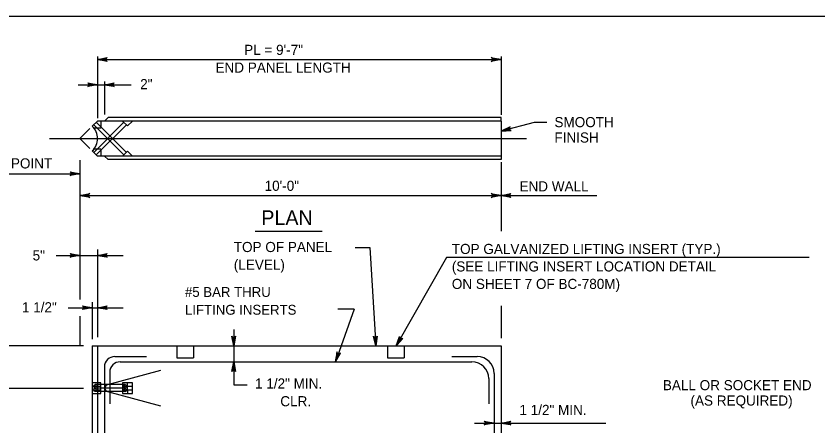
# Model space of a CAD drawing. Extents: x 3385 to 6532, y -616 to 1166.
# Drawn here: x 5875.8 to 6119.6, y 432.2 to 556.7 of the extents above; entities that cross this region are included whole.
import ezdxf

# ---------------------------------------------------------------- set-up
doc = ezdxf.new("R2010")
doc.units = 0
doc.layers.add('1', color=7, linetype='Continuous')
doc.layers.add('2', color=7, linetype='Continuous')

msp = doc.modelspace()

# ---------------------------------------------------------------- linework, layer by layer
at = {"layer": '1'}
for p, q in [((5900.6, 544.41), (5900.6, 525.64)), ((6023.26, 544.41), (6023.26, 526.72)), ((5900.6, 543.5), (6023.26, 543.5)), ((5902.73, 536.78), (5902.73, 526.81)), ((5894.73, 535.82), (5910.81, 535.82)), ((5899.03, 523.25), (5900.6, 524.82)), ((5899.45, 515.31), (5908.61, 524.46)), ((5900.24, 524.46), (5909.4, 515.31)), ((6023.26, 524.82), (5900.6, 524.82)), ((5901.65, 524.82), (5901.65, 522.69)), ((5902.73, 524.82), (5903.8, 525.89)), ((6023.26, 525.89), (5903.8, 525.89)), ((5909.76, 523.31), (5908.25, 524.82)), ((5909.76, 523.31), (5911.27, 524.82)), ((6023.26, 524.82), (6023.26, 525.89)), ((6023.26, 524.82), (6023.26, 514.16)), ((6033.37, 524.4), (6023.26, 521.72)), ((6037.2, 524.4), (6033.37, 524.4)), ((5895.27, 519.49), (5898.3, 522.53)), ((5899.45, 523.67), (5908.61, 514.51)), ((5901.65, 522.69), (5899.52, 522.69)), ((5900.24, 514.51), (5909.4, 523.67)), ((5886.06, 519.49), (6030.95, 519.49)), ((5895.27, 519.49), (5898.3, 516.46)), ((5899.03, 515.73), (5900.6, 514.16)), ((5901.65, 516.29), (5899.52, 516.29)), ((5901.65, 516.29), (5901.65, 514.16)), ((5909.76, 515.66), (5908.25, 514.16)), ((5909.76, 515.66), (5911.27, 514.16)), ((5895.27, 512.95), (5895.27, 470.58)), ((6023.26, 514.16), (5900.6, 514.16)), ((5902.73, 514.16), (5903.8, 513.09)), ((6023.26, 513.09), (5903.8, 513.09)), ((6023.26, 514.16), (6023.26, 513.09)), ((6023.26, 512.28), (6023.26, 491.33)), ((5860.61, 508.82), (5895.27, 508.82)), ((5895.27, 502.2), (6023.26, 502.2)), ((6023.26, 502.2), (6052.41, 502.2)), ((5948.5, 491.37), (5968.87, 491.37)), ((5900.59, 485.76), (5900.59, 459.17)), ((5978.88, 486.43), (5983.34, 486.43)), ((5983.34, 486.43), (5985.2, 456.51)), ((5888.09, 484.02), (5908.38, 484.02)), ((6006.69, 483.34), (5991.43, 456.51)), ((6116.94, 483.34), (6006.69, 483.34)), ((5891.74, 468.14), (5908.38, 468.14)), ((5899.03, 469.79), (5899.03, 458.62)), ((6023.26, 468.68), (6023.26, 458.93)), ((5895.27, 465.6), (5895.27, 456.83)), ((5978.57, 467.64), (5972.94, 451.71)), ((5978.57, 467.64), (5973.68, 467.64)), ((5942, 461.55), (5942, 444.73)), ((5896.39, 456.51), (5848.64, 456.51)), ((5899.03, 456.51), (6023.26, 456.51)), ((5899.03, 456.51), (5899.03, 301.32)), ((5900.59, 456.51), (5900.59, 301.32)), ((5924.71, 456.51), (5924.71, 452.93)), ((5929.83, 456.51), (5929.83, 452.93)), ((5988.7, 456.51), (5988.7, 452.93)), ((5993.82, 456.51), (5993.82, 452.93)), ((6023.26, 456.51), (6023.26, 301.32)), ((5905.92, 453.31), (5915.52, 453.31)), ((5907.52, 451.71), (6014.41, 451.71)), ((5924.71, 452.93), (5929.83, 452.93)), ((5988.7, 452.93), (5993.82, 452.93)), ((6008.33, 453.31), (6016.01, 453.31)), ((5902.72, 450.11), (5902.72, 307.72)), ((5919.73, 449.05), (5903.62, 444.73)), ((5904.32, 448.51), (5904.32, 438.91)), ((6019.53, 446.59), (6019.53, 438.91)), ((6021.13, 448.19), (6021.13, 309.64)), ((5848.87, 443.71), (5896.39, 443.71)), ((5909, 444.78), (5899.85, 444.78)), ((5909, 443.71), (5899.85, 443.71)), ((5909.76, 443.18), (5909.76, 445.31)), ((5942, 444.73), (5946.05, 444.73)), ((5909, 442.65), (5899.85, 442.65)), ((5903.62, 442.67), (5919.73, 438.35)), ((5909.76, 443.18), (5909.76, 442.11)), ((6015.17, 433.1), (6055.09, 433.1))]:
    msp.add_line(p, q, dxfattribs=at)
for points in [[(5900.6, 543.5), (5903.58, 544.06), (5903.35, 543.9), (5903.23, 543.7), (5903.2, 543.5), (5903.23, 543.3), (5903.35, 543.1), (5903.58, 542.94), (5900.6, 543.5), (5903.35, 543.1), (5903.23, 543.3), (5900.6, 543.5), (5903.2, 543.5), (5903.23, 543.7), (5900.6, 543.5), (5903.35, 543.9)], [(6023.26, 543.5), (6020.28, 542.94), (6020.51, 543.1), (6020.63, 543.3), (6020.66, 543.5), (6020.63, 543.7), (6020.51, 543.9), (6020.28, 544.06), (6023.26, 543.5), (6020.51, 543.9), (6020.63, 543.7), (6023.26, 543.5), (6020.66, 543.5), (6020.63, 543.3), (6023.26, 543.5), (6020.51, 543.1)], [(5900.6, 535.82), (5897.62, 535.26), (5897.85, 535.42), (5897.96, 535.62), (5898, 535.82), (5897.96, 536.02), (5897.85, 536.22), (5897.62, 536.38), (5900.6, 535.82), (5897.85, 536.22), (5897.96, 536.02), (5900.6, 535.82), (5898, 535.82), (5897.96, 535.62), (5900.6, 535.82), (5897.85, 535.42)], [(5902.73, 535.82), (5905.72, 536.38), (5905.49, 536.22), (5905.37, 536.02), (5905.33, 535.82), (5905.37, 535.62), (5905.49, 535.42), (5905.72, 535.26), (5902.73, 535.82), (5905.49, 535.42), (5905.37, 535.62), (5902.73, 535.82), (5905.33, 535.82), (5905.37, 536.02), (5902.73, 535.82), (5905.49, 536.22)], [(6023.26, 521.72), (6026.29, 521.95), (6026.16, 521.99), (6026.03, 522.04), (6025.94, 522.12), (6025.86, 522.2), (6025.82, 522.3), (6025.78, 522.39), (6025.77, 522.49), (6025.76, 522.59), (6025.79, 522.7), (6025.82, 522.81), (6025.91, 522.92), (6026, 523.03), (6023.26, 521.72), (6025.91, 522.92), (6025.82, 522.81), (6023.26, 521.72), (6025.79, 522.7), (6025.76, 522.59), (6023.26, 521.72), (6025.77, 522.49), (6025.78, 522.39), (6023.26, 521.72), (6025.82, 522.3), (6025.86, 522.2), (6023.26, 521.72), (6025.94, 522.12), (6026.03, 522.04), (6023.26, 521.72), (6026.16, 521.99)], [(5895.27, 508.82), (5892.28, 508.26), (5892.51, 508.42), (5892.63, 508.62), (5892.67, 508.82), (5892.63, 509.02), (5892.51, 509.22), (5892.28, 509.38), (5895.27, 508.82), (5892.51, 509.22), (5892.63, 509.02), (5895.27, 508.82), (5892.67, 508.82), (5892.63, 508.62), (5895.27, 508.82), (5892.51, 508.42)], [(5895.27, 502.2), (5898.25, 502.76), (5898.02, 502.6), (5897.9, 502.4), (5897.87, 502.2), (5897.9, 502), (5898.02, 501.8), (5898.25, 501.64), (5895.27, 502.2), (5898.02, 501.8), (5897.9, 502), (5895.27, 502.2), (5897.87, 502.2), (5897.9, 502.4), (5895.27, 502.2), (5898.02, 502.6)], [(6023.26, 502.2), (6020.28, 501.64), (6020.51, 501.8), (6020.63, 502), (6020.66, 502.2), (6020.63, 502.4), (6020.51, 502.6), (6020.28, 502.76), (6023.26, 502.2), (6020.51, 502.6), (6020.63, 502.4), (6023.26, 502.2), (6020.66, 502.2), (6020.63, 502), (6023.26, 502.2), (6020.51, 501.8)], [(6023.26, 502.2), (6026.25, 502.76), (6026.02, 502.6), (6025.9, 502.4), (6025.86, 502.2), (6025.9, 502), (6026.02, 501.8), (6026.25, 501.64), (6023.26, 502.2), (6026.02, 501.8), (6025.9, 502), (6023.26, 502.2), (6025.86, 502.2), (6025.9, 502.4), (6023.26, 502.2), (6026.02, 502.6)], [(5895.27, 484.02), (5892.28, 483.46), (5892.51, 483.62), (5892.63, 483.82), (5892.67, 484.02), (5892.63, 484.22), (5892.51, 484.42), (5892.28, 484.58), (5895.27, 484.02), (5892.51, 484.42), (5892.63, 484.22), (5895.27, 484.02), (5892.67, 484.02), (5892.63, 483.82), (5895.27, 484.02), (5892.51, 483.62)], [(5900.59, 484.02), (5903.57, 484.58), (5903.34, 484.42), (5903.22, 484.22), (5903.19, 484.02), (5903.22, 483.82), (5903.34, 483.62), (5903.57, 483.46), (5900.59, 484.02), (5903.34, 483.62), (5903.22, 483.82), (5900.59, 484.02), (5903.19, 484.02), (5903.22, 484.22), (5900.59, 484.02), (5903.34, 484.42)], [(5899.03, 468.14), (5896.05, 467.58), (5896.28, 467.74), (5896.39, 467.94), (5896.43, 468.14), (5896.39, 468.34), (5896.28, 468.54), (5896.05, 468.7), (5899.03, 468.14), (5896.28, 468.54), (5896.39, 468.34), (5899.03, 468.14), (5896.43, 468.14), (5896.39, 467.94), (5899.03, 468.14), (5896.28, 467.74)], [(5900.59, 468.14), (5903.57, 468.7), (5903.34, 468.54), (5903.22, 468.34), (5903.19, 468.14), (5903.22, 467.94), (5903.34, 467.74), (5903.57, 467.58), (5900.59, 468.14), (5903.34, 467.74), (5903.22, 467.94), (5900.59, 468.14), (5903.19, 468.14), (5903.22, 468.34), (5900.59, 468.14), (5903.34, 468.54)], [(5942, 456.51), (5941.45, 459.5), (5941.52, 459.38), (5941.6, 459.27), (5941.7, 459.21), (5941.8, 459.15), (5941.9, 459.13), (5942, 459.11), (5942.1, 459.13), (5942.2, 459.15), (5942.3, 459.21), (5942.4, 459.27), (5942.48, 459.38), (5942.56, 459.5), (5942, 456.51), (5942.48, 459.38), (5942.4, 459.27), (5942, 456.51), (5942.3, 459.21), (5942.2, 459.15), (5942, 456.51), (5942.1, 459.13), (5942, 459.11), (5942, 456.51), (5941.9, 459.13), (5941.8, 459.15), (5942, 456.51), (5941.7, 459.21), (5941.6, 459.27), (5942, 456.51), (5941.52, 459.38)], [(5985.2, 456.51), (5984.46, 459.46), (5984.54, 459.35), (5984.63, 459.24), (5984.73, 459.18), (5984.84, 459.13), (5984.94, 459.12), (5985.04, 459.11), (5985.14, 459.13), (5985.24, 459.15), (5985.33, 459.22), (5985.43, 459.29), (5985.5, 459.41), (5985.57, 459.52), (5985.2, 456.51), (5985.5, 459.41), (5985.43, 459.29), (5985.2, 456.51), (5985.33, 459.22), (5985.24, 459.15), (5985.2, 456.51), (5985.14, 459.13), (5985.04, 459.11), (5985.2, 456.51), (5984.94, 459.12), (5984.84, 459.13), (5985.2, 456.51), (5984.73, 459.18), (5984.63, 459.24), (5985.2, 456.51), (5984.54, 459.35)], [(5991.43, 456.51), (5992.42, 459.38), (5992.44, 459.24), (5992.45, 459.1), (5992.51, 459), (5992.56, 458.9), (5992.64, 458.84), (5992.72, 458.77), (5992.82, 458.74), (5992.91, 458.7), (5993.03, 458.71), (5993.14, 458.71), (5993.27, 458.77), (5993.4, 458.83), (5991.43, 456.51), (5993.27, 458.77), (5993.14, 458.71), (5991.43, 456.51), (5993.03, 458.71), (5992.91, 458.7), (5991.43, 456.51), (5992.82, 458.74), (5992.72, 458.77), (5991.43, 456.51), (5992.64, 458.84), (5992.56, 458.9), (5991.43, 456.51), (5992.51, 459), (5992.45, 459.1), (5991.43, 456.51), (5992.44, 459.24)], [(5972.94, 451.71), (5974.46, 454.34), (5974.23, 454.18), (5974, 454.13), (5973.8, 454.16), (5973.63, 454.26), (5973.48, 454.44), (5973.4, 454.71), (5972.94, 451.71), (5973.48, 454.44), (5973.63, 454.26), (5972.94, 451.71), (5973.8, 454.16), (5974, 454.13), (5972.94, 451.71), (5974.23, 454.18)], [(5942, 451.71), (5942.56, 448.73), (5942.48, 448.85), (5942.4, 448.96), (5942.3, 449.02), (5942.2, 449.08), (5942.1, 449.1), (5942, 449.11), (5941.9, 449.1), (5941.8, 449.08), (5941.7, 449.02), (5941.6, 448.96), (5941.52, 448.85), (5941.45, 448.73), (5942, 451.71), (5941.52, 448.85), (5941.6, 448.96), (5942, 451.71), (5941.7, 449.02), (5941.8, 449.08), (5942, 451.71), (5941.9, 449.1), (5942, 449.11), (5942, 451.71), (5942.1, 449.1), (5942.2, 449.08), (5942, 451.71), (5942.3, 449.02), (5942.4, 448.96), (5942, 451.71), (5942.48, 448.85)], [(6021.13, 433.1), (6018.15, 432.54), (6018.38, 432.7), (6018.5, 432.9), (6018.53, 433.1), (6018.5, 433.3), (6018.38, 433.5), (6018.15, 433.66), (6021.13, 433.1), (6018.38, 433.5), (6018.5, 433.3), (6021.13, 433.1), (6018.53, 433.1), (6018.5, 432.9), (6021.13, 433.1), (6018.38, 432.7)], [(6023.26, 433.1), (6026.25, 433.66), (6026.02, 433.5), (6025.9, 433.3), (6025.86, 433.1), (6025.9, 432.9), (6026.02, 432.7), (6026.25, 432.54), (6023.26, 433.1), (6026.02, 432.7), (6025.9, 432.9), (6023.26, 433.1), (6025.86, 433.1), (6025.9, 433.3), (6023.26, 433.1), (6026.02, 433.5)]]:
    msp.add_lwpolyline(points, dxfattribs=at)
for points in [[(5899.03, 443.18), (5901.65, 443.18), (5901.65, 445.31), (5899.03, 445.31)], [(5899.03, 442.11), (5901.65, 442.11), (5901.65, 444.24), (5899.03, 444.24)], [(5908.25, 443.18), (5911.27, 443.18), (5911.27, 445.31), (5908.25, 445.31)], [(5908.25, 442.11), (5911.27, 442.11), (5911.27, 444.24), (5908.25, 444.24)]]:
    msp.add_lwpolyline(points, close=True, dxfattribs=at)
for centre, radius, start, end in [((5895.27, 519.49), 5.32, 314.9993, 45.0018), ((5905.92, 450.11), 3.2, 90, 180), ((5907.52, 448.51), 3.2, 90, 180), ((6014.41, 446.59), 5.12, 0, 90), ((6016.01, 448.19), 5.12, 0, 90), ((5903.89, 443.7), 1.07, 105, 255)]:
    msp.add_arc(centre, radius, start, end, dxfattribs=at)
for centre, major_axis, ratio in [((5899.85, 444.24), (0, 0.534), 0.741868), ((5899.85, 443.18), (0, 0.531), 0.745444), ((5909, 444.25), (0, 0.534), 0.741868), ((5909, 443.17), (0, 0.534), 0.741868)]:
    msp.add_ellipse(centre, major_axis=major_axis, ratio=ratio, dxfattribs=at)
at = {"layer": '2'}
msp.add_line((5483.34, 556.69), (6269.34, 556.69), dxfattribs=at)

# ---------------------------------------------------------------- texts
at = {"layer": '1'}
for s, height, p in [('PL = 9\'-7"', 3.072, (5945.18, 544.89)), ('END PANEL LENGTH', 3.072, (5936.47, 539.51)), ('2"', 3.072, (5913.58, 534.49)), ('SMOOTH', 3.072, (6039.49, 522.95)), ('FINISH', 3.072, (6039.49, 518.28)), ('BEND POINT', 3.072, (5861.74, 510.42)), ('10\'-0"', 3.072, (5951.4, 503.62)), ('END WALL', 3.072, (6028.87, 503.45)), ('PLAN', 4.477, (5950.39, 493.22)), ('TOP OF PANEL', 3.072, (5942.03, 485.03)), ('TOP GALVANIZED LIFTING INSERT (TYP.) ', 3.072, (6008.3, 484.44)), ('5"', 3.072, (5880.89, 482.48)), ('(LEVEL)', 3.072, (5942.03, 479.66)), ('(SEE LIFTING INSERT LOCATION DETAIL ', 3.072, (6008.3, 479.13)), ('ON SHEET 7 OF BC-780M)', 3.072, (6008.3, 473.82)), ('#5 BAR THRU', 3, (5927.19, 471.4)), ('1 1/2"', 3.072, (5877.64, 466.73)), ('LIFTING INSERTS', 3, (5927.19, 466)), ('1 1/2" MIN.', 3.072, (5948.49, 443.58)), ('BALL OR SOCKET END', 3.0721, (6072.44, 443.08)), ('CLR.', 3.072, (5956.17, 438.2)), ('(AS REQUIRED)', 3.0721, (6080.84, 438.41)), ('1 1/2" MIN.', 3.072, (6028.85, 435.56))]:
    msp.add_text(s, height=height, dxfattribs=at).set_placement(p)

doc.saveas('drawing.dxf')
